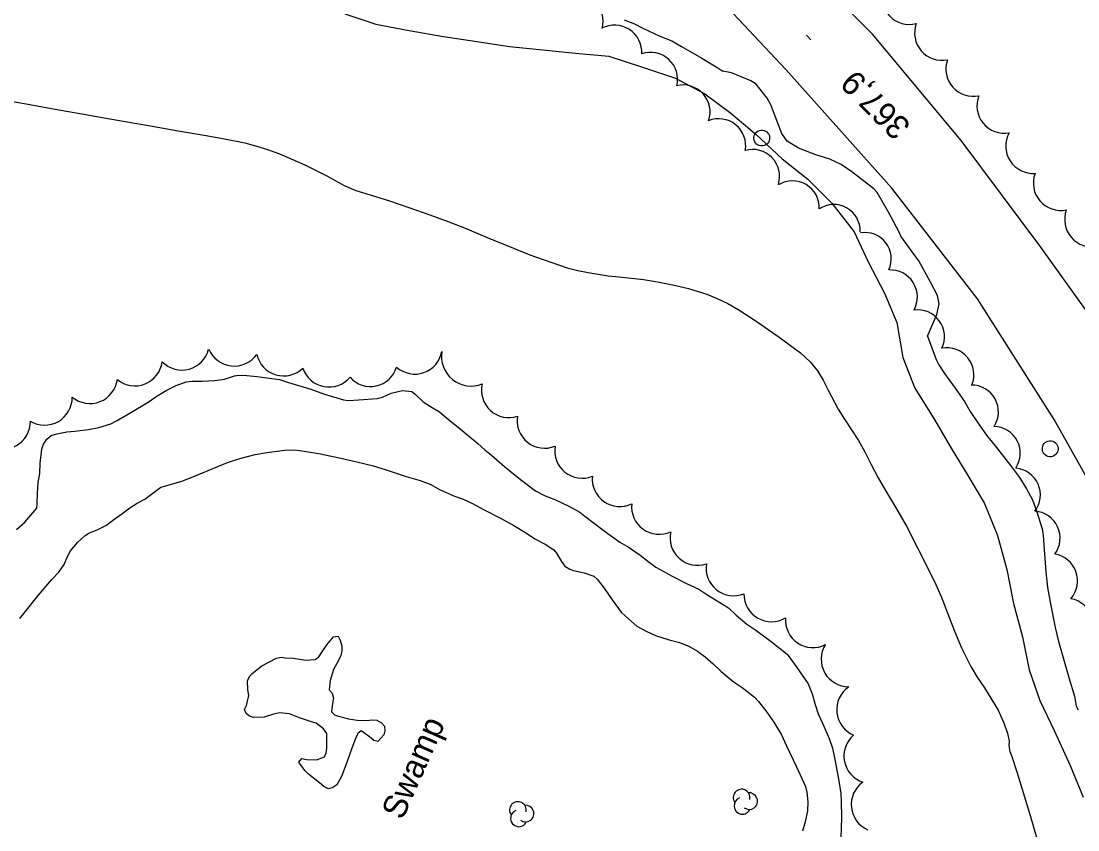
# Model space of a CAD drawing. Extents: x 287698 to 290158, y 5234163 to 5237182.
# Drawn here: x 288721 to 288854, y 5235640.7 to 5235742.5 of the extents above; entities that cross this region are included whole.
import ezdxf

# ---------------------------------------------------------------- set-up
doc = ezdxf.new("R2010")
doc.units = 0
for name, color, linetype in [('Niveau 2', 7, 'Continuous'), ('Niveau 21', 7, 'Continuous'), ('Niveau 3', 7, 'Continuous'), ('Niveau 36', 7, 'Continuous'), ('Niveau 4', 7, 'Continuous'), ('Niveau 44', 7, 'Continuous'), ('Niveau 7', 7, 'Continuous')]:
    doc.layers.add(name, color=color, linetype=linetype)

msp = doc.modelspace()

# ---------------------------------------------------------------- linework, layer by layer
at = {"layer": 'Niveau 2'}
for points in [[(288761.76, 5235743.4), (288765.67, 5235742.11), (288769.86, 5235741.3), (288774.17, 5235740.54), (288778.36, 5235739.91), (288782.47, 5235739.29), (288786.69, 5235738.89), (288790.77, 5235738.46), (288794.97, 5235738.07), (288798.97, 5235736.78), (288803.36, 5235735.3), (288807.06, 5235733.36), (288810.31, 5235730.92), (288813.49, 5235728.22), (288816.8, 5235725.15), (288820.01, 5235722.62), (288823.01, 5235719.57), (288825.82, 5235715.99), (288827.59, 5235712.21), (288829.67, 5235708.28), (288831.19, 5235704.57), (288831.98, 5235700.19), (288833.46, 5235696.31), (288835.86, 5235692.5), (288838.03, 5235688.78), (288840.15, 5235685.33), (288842.24, 5235681.79), (288843.89, 5235677.79), (288845.04, 5235673.49), (288845.88, 5235669.24), (288847, 5235665.03), (288847.87, 5235660.89), (288849.2, 5235657.03), (288851.01, 5235653.24), (288853.01, 5235648.84), (288854.63, 5235644.88)], [(288796.9, 5235742.64), (288798.22, 5235742.15), (288799.25, 5235741.62), (288801.39, 5235740.62), (288802.92, 5235740), (288804.11, 5235739.29), (288806.68, 5235737.83), (288808.69, 5235736.61), (288809.33, 5235736.18)], [(288835.06, 5235702.85), (288836.22, 5235705.57), (288836.55, 5235706.92), (288836.32, 5235707.98), (288835.46, 5235709.64), (288833.99, 5235712.33), (288833.47, 5235713.02), (288831.7, 5235715.42), (288831.51, 5235715.96), (288830.15, 5235718.44), (288828.73, 5235720.93), (288828.3, 5235721.4), (288825.55, 5235723.55), (288824.2, 5235724.45), (288822.76, 5235725.11), (288821.03, 5235725.67), (288818.85, 5235726.52), (288817.42, 5235727.38), (288816.72, 5235728.35), (288816.34, 5235729.44), (288815.36, 5235731.95), (288814.9, 5235732.81), (288813.49, 5235734.55), (288812.85, 5235734.99), (288810.42, 5235735.99), (288809.33, 5235736.18)], [(288719.01, 5235732.54), (288722.15, 5235731.99), (288725.78, 5235731.35), (288728.92, 5235730.79), (288731.49, 5235730.34), (288734.14, 5235729.87), (288737.31, 5235729.31), (288740.8, 5235728.7), (288744.05, 5235728.13), (288746.64, 5235727.67), (288749.17, 5235727.16), (288750.54, 5235726.8), (288752.05, 5235726.34), (288753.54, 5235725.8), (288755.11, 5235725.14), (288756.73, 5235724.41), (288759.51, 5235723.01), (288761.66, 5235721.83), (288763.13, 5235721.2), (288764.41, 5235720.8), (288767.36, 5235719.9), (288769.8, 5235719.04), (288772.44, 5235718.14), (288774.86, 5235717.26), (288776.81, 5235716.49), (288779.67, 5235715.29), (288782.06, 5235714.29), (288785.03, 5235713.11), (288786.72, 5235712.52), (288789.74, 5235711.46), (288791.07, 5235711.1), (288792.37, 5235710.85), (288794.91, 5235710.44), (288796.27, 5235710.32), (288799.33, 5235709.99), (288801.08, 5235709.68), (288803.41, 5235709.23), (288804.99, 5235708.84), (288807.3, 5235708.14), (288808.62, 5235707.6), (288809.93, 5235706.97), (288811.23, 5235706.23), (288812.65, 5235705.33), (288814.18, 5235704.29), (288816.41, 5235702.75), (288819.07, 5235700.78), (288820.29, 5235699.64), (288821.24, 5235698.49), (288821.96, 5235697.31), (288822.56, 5235696.08), (288823.82, 5235693.66), (288824.62, 5235692.43), (288826.37, 5235689.74), (288827.18, 5235688.29), (288827.97, 5235686.7), (288828.87, 5235685.04), (288829.8, 5235683.43), (288831.06, 5235681.35), (288832.43, 5235678.94), (288833.82, 5235676.25), (288835.21, 5235673.51), (288836.13, 5235671.6)], [(288835.06, 5235702.85), (288836.14, 5235699.92), (288836.5, 5235699.27), (288837.22, 5235698.17), (288838.55, 5235696.33), (288839.7, 5235694.64), (288840.45, 5235693.37), (288841.38, 5235691.97), (288842.5, 5235690.4), (288843.73, 5235688.86), (288845.52, 5235686.59), (288846.64, 5235685.06), (288847.54, 5235683.66), (288848.26, 5235682.28), (288848.76, 5235680.87), (288849.5, 5235678.6), (288849.61, 5235677.77), (288849.75, 5235676.01), (288849.96, 5235673.23), (288850.18, 5235671.24), (288850.55, 5235669.2), (288851.14, 5235666.19), (288851.55, 5235664.43), (288852, 5235662.87), (288852.83, 5235659.9), (288853.56, 5235657.56), (288853.77, 5235656.32), (288854, 5235655.83)], [(288836.13, 5235671.6), (288836.78, 5235670.09), (288837.4, 5235668.46), (288838.48, 5235665.73), (288839.36, 5235663.66), (288840.51, 5235661.3), (288841.32, 5235659.94), (288842.22, 5235658.61), (288843.97, 5235655.81), (288844.64, 5235654.3), (288845.12, 5235652.9), (288845.34, 5235651.89), (288845.31, 5235651.36), (288845.43, 5235650.61), (288845.67, 5235649.97), (288846.32, 5235648.05), (288846.97, 5235645.87), (288847.84, 5235642.96), (288848.78, 5235639.82)]]:
    msp.add_lwpolyline(points, dxfattribs=at)
at = {"layer": 'Niveau 21'}
for points in [[(288930.12, 5235481.92), (288923.96, 5235498.58), (288917.4, 5235516.56), (288911.7, 5235532.16), (288905.14, 5235550.55), (288898.43, 5235571.09), (288892.3, 5235587.97), (288884.77, 5235607.98), (288876.58, 5235630.61), (288870.03, 5235650.2), (288863.94, 5235666.55), (288857.87, 5235680.15), (288851, 5235692.38), (288841.37, 5235707.56), (288830.57, 5235721.47), (288817.25, 5235736.39), (288805.35, 5235749.11), (288792.27, 5235761.66), (288777.13, 5235774.32), (288762.23, 5235785.22), (288748.23, 5235793.37), (288734.09, 5235801.03), (288722.53, 5235805.81), (288711.22, 5235807.49)], [(288859.18, 5235700.28), (288849.31, 5235714.05), (288839.31, 5235727.47), (288828.15, 5235740.86), (288815.4, 5235753.66)]]:
    msp.add_lwpolyline(points, dxfattribs=at)
at = {"layer": 'Niveau 3'}
msp.add_line((288820.4, 5235740.15), (288819.85, 5235740.73), dxfattribs=at)
at = {"layer": 'Niveau 36'}
for centre in [(288814.21, 5235727.79), (288850.51, 5235688.69)]:
    msp.add_ellipse(centre, major_axis=(0.994, -0.109), ratio=0.999984, dxfattribs=at)
at = {"layer": 'Niveau 4'}
for points in [[(288723.08, 5235683.11), (288723.18, 5235684.44), (288723.38, 5235685.58), (288723.41, 5235686.89), (288723.62, 5235688.64), (288723.85, 5235689.27), (288724.27, 5235689.88), (288724.83, 5235690.35), (288725.54, 5235690.56), (288726.77, 5235690.81), (288727.78, 5235690.9), (288729.52, 5235691.12), (288730.79, 5235691.38), (288732.33, 5235691.83), (288733.04, 5235692.22), (288734.85, 5235693.26), (288737.01, 5235694.56), (288738.16, 5235695.34), (288739.37, 5235696.07), (288740.56, 5235696.66), (288741.81, 5235697.11), (288742.54, 5235697.18), (288743.82, 5235697.19), (288745.4, 5235697.29), (288746.61, 5235697.46), (288747.88, 5235697.88), (288748.38, 5235697.95), (288749.44, 5235697.91), (288750.67, 5235697.77), (288753.54, 5235697.39), (288754.69, 5235697.05), (288757.48, 5235696.18), (288759.19, 5235695.58), (288761.58, 5235694.84), (288762.23, 5235694.78), (288763.53, 5235694.84), (288765.81, 5235695), (288766.48, 5235695.19), (288767.6, 5235695.7), (288769, 5235696.04), (288770.21, 5235695.91), (288770.6, 5235695.58), (288771.62, 5235694.61), (288772.52, 5235694.01), (288773.68, 5235693.32), (288774.58, 5235692.54), (288776.03, 5235691.4), (288778.51, 5235689.35), (288779.36, 5235688.54), (288780.21, 5235687.87), (288781.84, 5235686.46), (288783.88, 5235684.81), (288785.75, 5235683.4), (288786.98, 5235682.77), (288788.18, 5235682.3), (288790.03, 5235681.43), (288791.32, 5235680.7), (288791.96, 5235680.2), (288794.37, 5235678.38), (288796.36, 5235676.95), (288797.53, 5235676.28), (288798.91, 5235675.32), (288799.86, 5235674.54), (288800.89, 5235673.79), (288801.83, 5235673.31), (288802.95, 5235672.66), (288804.76, 5235671.73), (288806.29, 5235671.01), (288807.32, 5235670.38), (288810.01, 5235668.69), (288811, 5235667.78), (288812.35, 5235666.64), (288813.45, 5235665.86), (288815.39, 5235664.44), (288817.39, 5235662.84), (288817.87, 5235662.24), (288818.54, 5235661.29), (288820.04, 5235659.11), (288820.56, 5235657.88), (288820.93, 5235656.52), (288821.32, 5235655.36), (288821.87, 5235654.17), (288822.7, 5235652.23), (288823.12, 5235651.04), (288823.36, 5235649.81), (288823.88, 5235647.19), (288824.16, 5235645.34), (288824.22, 5235644.32), (288824.26, 5235642.31), (288824.2, 5235640.96), (288824.13, 5235638.6)], [(288736.59, 5235682.37), (288738.63, 5235683.86), (288739.26, 5235684.03), (288741.27, 5235684.63), (288742.63, 5235685.16), (288744.57, 5235685.97), (288747.01, 5235686.97), (288748.53, 5235687.47), (288750.5, 5235687.97), (288751.94, 5235688.21), (288754.2, 5235688.53), (288755.49, 5235688.56), (288756.66, 5235688.41), (288758.71, 5235688.06), (288761.26, 5235687.53), (288763.26, 5235687.07), (288765.21, 5235686.58), (288766.98, 5235686.04), (288769.49, 5235685.22), (288771.23, 5235684.7), (288772.58, 5235684.2), (288773.66, 5235683.58), (288775.55, 5235682.74), (288776.65, 5235682.35), (288777.89, 5235681.78), (288779.14, 5235681.1), (288781.42, 5235679.91), (288783.02, 5235679.02), (288784.62, 5235678.08), (288785.67, 5235677.38), (288786.95, 5235676.7), (288788.06, 5235675.96), (288788.41, 5235675.56), (288789.01, 5235674.49), (288789.45, 5235673.93), (288790.06, 5235673.55), (288790.54, 5235673.37), (288791.86, 5235673.07), (288793.09, 5235672.65), (288793.49, 5235672.29), (288794.37, 5235671.17), (288795.39, 5235669.68), (288796.54, 5235668.14), (288797.08, 5235667.62), (288798.48, 5235666.39), (288799.68, 5235665.74), (288800.84, 5235665.21), (288802.58, 5235664.65), (288803.88, 5235664.33), (288805.04, 5235663.88), (288806.13, 5235663.22), (288807.09, 5235662.5), (288808.12, 5235661.64), (288809.1, 5235660.66), (288810.61, 5235659.41), (288811.73, 5235658.66), (288813.32, 5235657.46), (288813.81, 5235656.89), (288814.84, 5235655.57), (288815.75, 5235654.28), (288816.7, 5235652.69), (288817.3, 5235651.39), (288818.6, 5235648.7), (288819.71, 5235646.21), (288819.87, 5235645.48), (288820, 5235644.29), (288819.96, 5235643.13), (288819.69, 5235641.75), (288819.32, 5235640.6)], [(288720.45, 5235678.53), (288721.5, 5235679.48), (288722.99, 5235681.2), (288723.05, 5235681.82), (288723.08, 5235683.11)], [(288720.88, 5235667.32), (288721.56, 5235668.19), (288723.19, 5235670.22), (288724.91, 5235672.26), (288725.77, 5235673.17), (288726.46, 5235674.12), (288726.89, 5235675.24), (288727.26, 5235675.85), (288728.17, 5235676.93), (288729.08, 5235677.79), (288729.57, 5235678.06), (288730.68, 5235678.53), (288731.78, 5235679.08), (288732.68, 5235679.79), (288733.69, 5235680.49), (288734.7, 5235681.27), (288735.65, 5235681.83), (288736.59, 5235682.37)], [(288751.3, 5235661.39), (288753.17, 5235662.37), (288753.74, 5235662.47), (288754.25, 5235662.41), (288755.25, 5235662.33), (288756.87, 5235662.08), (288758.01, 5235662.2), (288758.47, 5235662.53), (288758.83, 5235663), (288759.48, 5235664.01), (288760.35, 5235665.02), (288760.92, 5235665.12), (288761.18, 5235664.63), (288761.37, 5235663.91), (288761.4, 5235663.27), (288761.25, 5235662.7), (288760.99, 5235662.14), (288760.34, 5235660.92), (288759.9, 5235659.55), (288759.78, 5235658.36), (288760.15, 5235657.95), (288760.35, 5235657.3), (288760.2, 5235656.64), (288760.09, 5235655.59), (288760.48, 5235655.23), (288760.98, 5235655.04), (288762.21, 5235654.7), (288763.33, 5235654.55), (288764.52, 5235654.49), (288765.18, 5235654.61), (288765.79, 5235654.53), (288766.36, 5235654.21), (288766.74, 5235653.78), (288766.81, 5235653.21), (288766.65, 5235652.72), (288765.93, 5235651.85), (288765.41, 5235651.98), (288764.88, 5235652.47), (288763.8, 5235653.2), (288763.41, 5235652.86), (288763.11, 5235652.24), (288762.64, 5235651.04), (288762.07, 5235649.34), (288761.32, 5235647.47), (288760.77, 5235646.42), (288760.25, 5235646.06), (288759.71, 5235645.93), (288759.1, 5235646.19), (288758.56, 5235646.67), (288757.19, 5235647.77), (288756.73, 5235648.23), (288755.97, 5235649.26), (288756.34, 5235649.72), (288756.92, 5235649.62), (288758.21, 5235649.57), (288759.2, 5235649.95), (288759.4, 5235650.42), (288759.51, 5235651.02), (288759.51, 5235652.87), (288759.09, 5235653.44), (288758.17, 5235654.19), (288757.68, 5235654.31), (288756.04, 5235654.83), (288754.81, 5235655.35), (288753.54, 5235655.47), (288752.79, 5235655.3), (288751.61, 5235654.94), (288750.27, 5235654.89), (288749.78, 5235655.05), (288749.33, 5235655.4), (288749.15, 5235655.89), (288749.37, 5235656.41), (288749.68, 5235657.67), (288749.55, 5235658.36), (288749.53, 5235659.51), (288749.75, 5235660.04), (288750.09, 5235660.42), (288751.3, 5235661.39)]]:
    msp.add_lwpolyline(points, dxfattribs=at)
at = {"layer": 'Niveau 44'}
for centre, radius, start, end in [((288836.88, 5235741), 3.44, 159.973, 281.6637), ((288840.82, 5235736.47), 3.44, 160.366, 282.0776), ((288844.73, 5235731.82), 3.44, 157.9501, 279.905), ((288848.37, 5235726.79), 3.46, 151.6444, 273.6897), ((288851.84, 5235722.13), 3.46, 159.7814, 281.5034), ((288855.78, 5235717.55), 3.46, 159.9404, 281.7549), ((288741.27, 5235702.05), 3.46, 224.3536, 346.1069), ((288770.57, 5235701.54), 3.45, 228.309, 350.0154), ((288777.65, 5235700.31), 3.73, 170.2354, 291.9159), ((288735.35, 5235700.08), 3.47, 230.5323, 352.545), ((288764.99, 5235699.96), 3.43, 221.2813, 343.3212), ((288759.77, 5235699.92), 3.46, 198.0939, 319.7698), ((288729.69, 5235697.87), 3.48, 230.2143, 352.3061), ((288782.4, 5235696.06), 3.45, 166.7416, 288.3659), ((288723.99, 5235695.13), 3.47, 238.7911, 1.0026), ((288786.89, 5235692.21), 3.45, 170.4164, 292.5012), ((288791.61, 5235688.44), 3.45, 170.3438, 292.0399), ((288796.34, 5235684.88), 3.45, 174.0633, 296.0304), ((288801.29, 5235681.38), 3.45, 173.3261, 295.2894), ((288806.13, 5235677.49), 3.46, 167.1928, 288.9736), ((288850.54, 5235672.07), 3.41, 319.0211, 80.83), ((288810.67, 5235673.65), 3.45, 170.4682, 292.1825), ((288815.43, 5235670.4), 3.46, 179.1164, 300.9708), ((288820.64, 5235667.13), 3.45, 175.0042, 297.0359), ((288825.17, 5235662.22), 3.48, 148.1746, 269.6782), ((288827.14, 5235655.88), 3.49, 124.7629, 246.9012), ((288828, 5235650.03), 3.45, 130.1943, 251.9785), ((288828.92, 5235643.93), 3.45, 125.2472, 247.1187)]:
    msp.add_arc(centre, radius, start, end, dxfattribs=at)
for centre, major_axis, ratio, start_param, end_param in [((288790.82, 5235742.51), (2.5, 2.36), 0.996374, 5.25137, 7.371747), ((288832.78, 5235745.51), (3.31, -0.95), 0.999995, 3.116419, 5.244813), ((288795.71, 5235738.58), (1.96, 2.79), 0.997851, 5.258604, 7.385214), ((288800.24, 5235735.18), (-2.5, 2.27), 0.999606, 3.63374, 5.791038), ((288804.33, 5235731.07), (0.67, 3.32), 0.998539, 4.57839, 6.72963), ((288808.79, 5235726.81), (2.14, 2.65), 0.99919, 5.218299, 7.347575), ((288813.07, 5235722.96), (-1.94, 2.78), 0.999512, 3.800343, 5.948481), ((288818.07, 5235719.01), (-0.72, 3.31), 0.999053, 4.4609, 6.610692), ((288823.25, 5235716.04), (0.9, 3.26), 0.991109, 4.968266, 7.121787), ((288827.16, 5235712.54), (2.24, 2.53), 0.983726, 5.015712, 7.169606), ((288830.38, 5235707.78), (2.98, 1.67), 0.998468, 5.270489, 7.395874), ((288833.82, 5235702.79), (-1.42, 3.07), 0.999414, 3.835282, 5.984626), ((288747.84, 5235702.58), (-0.38, -3.46), 0.999914, 5.224148, 7.347008), ((288754.06, 5235701.31), (3.35, 0.84), 0.999995, 3.113844, 5.245771), ((288837.51, 5235698.01), (-3.39, -0.07), 0.997679, 2.729229, 4.878886), ((288840.6, 5235693.32), (-1.64, 2.97), 0.999222, 3.637724, 5.787054), ((288718.71, 5235692.12), (1.72, -3.03), 0.999995, 5.221483, 7.350297), ((288843.33, 5235688.1), (3.01, 1.61), 0.993054, 5.214328, 7.33152), ((288845.85, 5235682.86), (3.11, 1.42), 0.993087, 5.215446, 7.331222), ((288848.34, 5235677.45), (3.3, 0.83), 0.999882, 5.403299, 7.53457), ((288852.52, 5235666.47), (3.21, 1.13), 0.99991, 5.218162, 7.34329), ((288811.68, 5235644.81), (-1.04, 0.14), 0.999986, 3.057798, 7.027673), ((288811.78, 5235643.77), (-1.04, 0.14), 0.999986, 5.184416, 9.123425), ((288812.63, 5235644.37), (-1.04, 0.14), 0.999986, 1.044869, 4.931445), ((288783.54, 5235643.24), (-1.04, 0.14), 0.999986, 3.057798, 7.027673), ((288783.64, 5235642.2), (-1.04, 0.14), 0.999986, 5.184416, 9.123425), ((288784.49, 5235642.8), (-1.04, 0.14), 0.999986, 1.044869, 4.931445)]:
    msp.add_ellipse(centre, major_axis=major_axis, ratio=ratio, start_param=start_param, end_param=end_param, dxfattribs=at)

# ---------------------------------------------------------------- texts
at = {"layer": 'Niveau 3'}
msp.add_text('367,9', height=3, rotation=134.8864, dxfattribs=at).set_placement((288833.11, 5235729.43))
at = {"layer": 'Niveau 7'}
msp.add_text('Swamp', height=3, rotation=66.1217, dxfattribs=at).set_placement((288769.01, 5235641.88))

doc.saveas('drawing.dxf')
